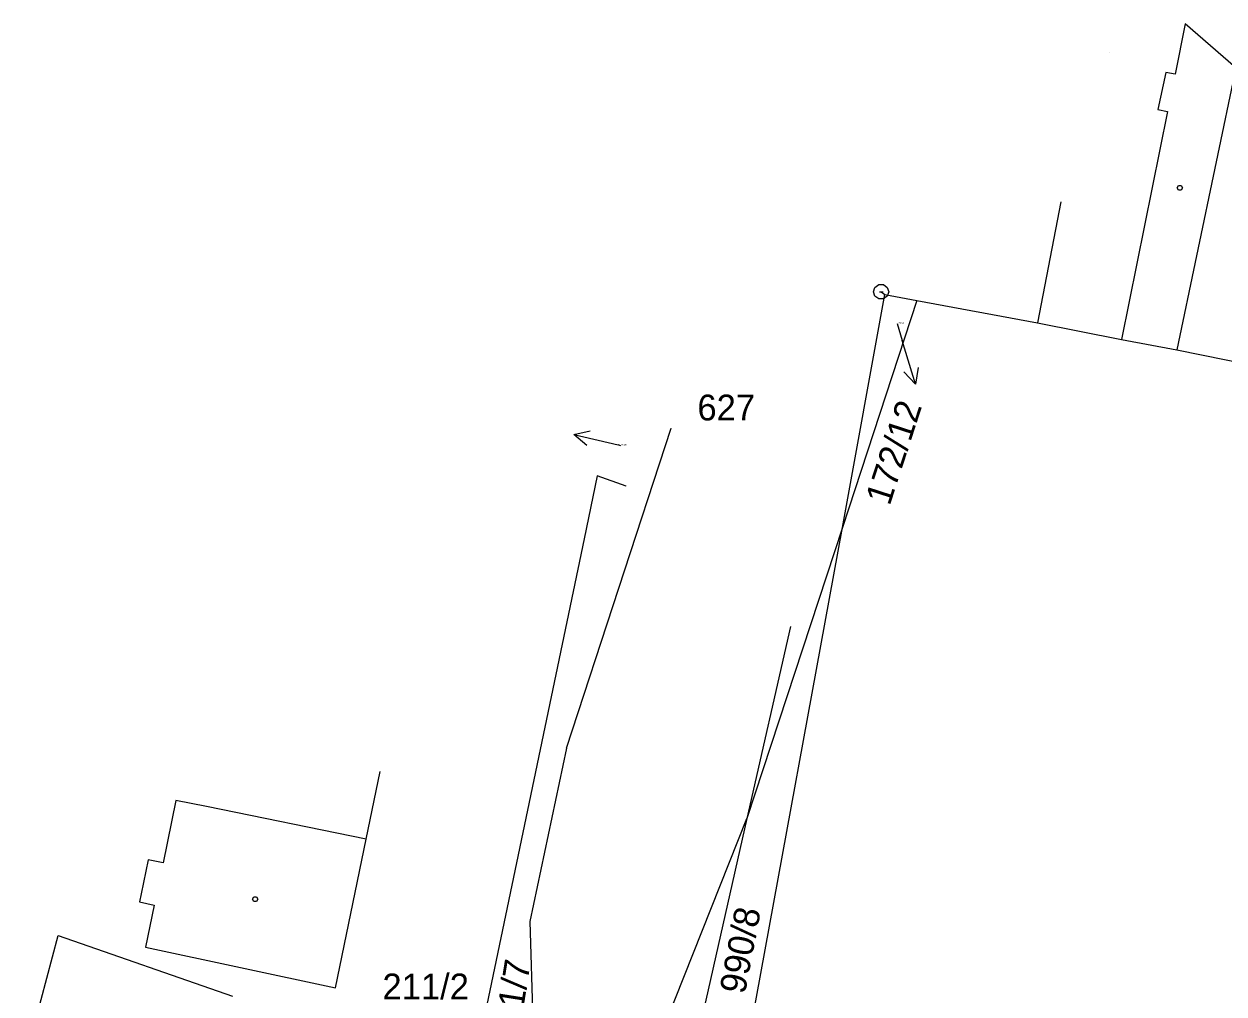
# Model space of a CAD drawing. Extents: x -755359 to -754474, y -1162585 to -1161655.
# Drawn here: x -755066.2 to -754987.3, y -1161776.6 to -1161712.8 of the extents above; entities that cross this region are included whole.
import ezdxf

# ---------------------------------------------------------------- set-up
doc = ezdxf.new("R2010")
doc.units = 0
for name, color, linetype in [('Vrstva 1', 7, 'Continuous'), ('Vrstva 12', 7, 'Continuous'), ('Vrstva 2', 7, 'Continuous'), ('Vrstva 4', 7, 'Continuous'), ('Vrstva 5', 7, 'Continuous'), ('Vrstva 7', 7, 'Continuous'), ('Vrstva 8', 7, 'Continuous')]:
    doc.layers.add(name, color=color, linetype=linetype)

msp = doc.modelspace()

# ---------------------------------------------------------------- linework, layer by layer
at = {"layer": 'Vrstva 1'}
for p, q in [((-754986.49, -1161715.65), (-754989.82, -1161712.77)), ((-754989.82, -1161712.77), (-754989.82, -1161712.77)), ((-754986.49, -1161715.65), (-754990.38, -1161734.22)), ((-755009.83, -1161730.4), (-755009.58, -1161730.57)), ((-755009.83, -1161730.4), (-755009.83, -1161730.4)), ((-755012.38, -1161745.91), (-755009.58, -1161730.57)), ((-755007.48, -1161730.96), (-755012.38, -1161745.91)), ((-755009.58, -1161730.57), (-755007.48, -1161730.96)), ((-755007.48, -1161730.96), (-754999.54, -1161732.44)), ((-754999.54, -1161732.44), (-754994.03, -1161733.53)), ((-754994.03, -1161733.53), (-754990.38, -1161734.22)), ((-754990.38, -1161734.22), (-754978.64, -1161736.57)), ((-755030.54, -1161760.43), (-755023.66, -1161739.37)), ((-755023.66, -1161739.37), (-755023.66, -1161739.37)), ((-755028.51, -1161742.5), (-755029.37, -1161746.66)), ((-755026.62, -1161743.19), (-755028.51, -1161742.5)), ((-755028.51, -1161742.5), (-755028.51, -1161742.5)), ((-755028.51, -1161742.5), (-755028.51, -1161742.5)), ((-755026.62, -1161743.19), (-755026.62, -1161743.19)), ((-755018.69, -1161780.44), (-755012.38, -1161745.91)), ((-755012.38, -1161745.91), (-755018.66, -1161765.05)), ((-755029.37, -1161746.66), (-755036.5, -1161780.73)), ((-755029.37, -1161746.66), (-755029.37, -1161746.66)), ((-755015.79, -1161752.42), (-755018.66, -1161765.05)), ((-755015.79, -1161752.42), (-755015.79, -1161752.42)), ((-755030.54, -1161760.43), (-755032.94, -1161771.83)), ((-755043.71, -1161766.41), (-755042.79, -1161761.96)), ((-755042.79, -1161761.96), (-755042.79, -1161761.96)), ((-755023.99, -1161778.44), (-755018.66, -1161765.05)), ((-755045.73, -1161776.2), (-755043.71, -1161766.41)), ((-755058.51, -1161770.01), (-755058.63, -1161770.54)), ((-755058.63, -1161770.54), (-755057.66, -1161770.75)), ((-755058.51, -1161770.01), (-755058.51, -1161770.01)), ((-755057.66, -1161770.75), (-755058.23, -1161773.52)), ((-755032.94, -1161771.83), (-755032.59, -1161783.86)), ((-755066.23, -1161781.24), (-755063.99, -1161772.75)), ((-755063.99, -1161772.75), (-755063.99, -1161772.75)), ((-755063.99, -1161772.75), (-755052.51, -1161776.75)), ((-755058.23, -1161773.52), (-755045.73, -1161776.2))]:
    msp.add_line(p, q, dxfattribs=at)
at = {"layer": 'Vrstva 12'}
for p, q in [((-754998, -1161724.47), (-754998, -1161724.47)), ((-754998, -1161724.47), (-754998, -1161724.47)), ((-755043.71, -1161766.41), (-755042.79, -1161761.96)), ((-755042.79, -1161761.96), (-755042.79, -1161761.96)), ((-755043.71, -1161766.41), (-755054.23, -1161764.27)), ((-755054.23, -1161764.27), (-755054.23, -1161764.27))]:
    msp.add_line(p, q, dxfattribs=at)
at = {"layer": 'Vrstva 4'}
for p, q in [((-754989.82, -1161712.77), (-754990.49, -1161716.08)), ((-754994.8, -1161714.66), (-754994.8, -1161714.66)), ((-754994.8, -1161714.66), (-754994.8, -1161714.66)), ((-754991.11, -1161715.96), (-754991.62, -1161718.4)), ((-754990.49, -1161716.08), (-754991.11, -1161715.96)), ((-754990.99, -1161718.52), (-754994.03, -1161733.53)), ((-754991.62, -1161718.4), (-754990.99, -1161718.52)), ((-754998, -1161724.47), (-754999.54, -1161732.44)), ((-754998, -1161724.47), (-754998, -1161724.47)), ((-754998, -1161724.47), (-754998, -1161724.47)), ((-755056.23, -1161763.86), (-755057.08, -1161767.98)), ((-755054.23, -1161764.27), (-755056.23, -1161763.86)), ((-755043.71, -1161766.41), (-755054.23, -1161764.27)), ((-755054.23, -1161764.27), (-755054.23, -1161764.27)), ((-755018.66, -1161765.05), (-755021.88, -1161779.23)), ((-755058.05, -1161767.78), (-755058.51, -1161770.01)), ((-755057.08, -1161767.98), (-755058.05, -1161767.78))]:
    msp.add_line(p, q, dxfattribs=at)
at = {"layer": 'Vrstva 5'}
for points in [[(-754990.09, -1161723.4), (-754990, -1161723.55), (-754990.09, -1161723.7), (-754990.27, -1161723.7), (-754990.36, -1161723.55), (-754990.27, -1161723.4)], [(-755050.93, -1161770.21), (-755050.84, -1161770.36), (-755050.93, -1161770.51), (-755051.11, -1161770.51), (-755051.2, -1161770.36), (-755051.11, -1161770.21)]]:
    msp.add_lwpolyline(points, close=True, dxfattribs=at)
at = {"layer": 'Vrstva 7'}
for p, q in [((-755008.79, -1161732.49), (-755008.45, -1161733.6)), ((-755007.574, -1161736.469), (-755008.45, -1161733.6)), ((-755030.063, -1161739.795), (-755027.14, -1161740.47)), ((-755026.95, -1161740.52), (-755027.14, -1161740.47))]:
    msp.add_line(p, q, dxfattribs=at)
for points in [[(-755007.388, -1161735.367), (-755007.574, -1161736.469), (-755008.344, -1161735.659)], [(-755029.201, -1161740.507), (-755030.063, -1161739.795), (-755028.976, -1161739.533)]]:
    msp.add_lwpolyline(points, dxfattribs=at)
at = {"layer": 'Vrstva 8'}
msp.add_line((-755009.95, -1161730.4), (-755009.71, -1161730.4), dxfattribs=at)
msp.add_lwpolyline([(-755009.68, -1161729.92), (-755009.43, -1161730.1), (-755009.33, -1161730.39), (-755009.43, -1161730.68), (-755009.68, -1161730.86), (-755009.99, -1161730.86), (-755010.24, -1161730.68), (-755010.34, -1161730.39), (-755010.24, -1161730.1), (-755009.99, -1161729.92)], close=True, dxfattribs=at)

# ---------------------------------------------------------------- texts
at = {"layer": 'Vrstva 2'}
for s, p in [('172/12', (-755008.767, -1161732.49)), ('991/8', (-755026.936, -1161740.52))]:
    msp.add_text(s, height=0.1, dxfattribs=at).set_placement(p)
msp.add_text('990/8', height=1.7, rotation=79.18277, dxfattribs=at).set_placement((-755018.805, -1161776.667))
at = {"layer": 'Vrstva 7'}
for s, rotation, p in [('172/12', 72.02079, (-755009.278, -1161744.523)), ('991/7', 81.01623, (-755033.773, -1161780.106))]:
    msp.add_text(s, height=1.7, rotation=rotation, dxfattribs=at).set_placement(p)
msp.add_text('211/2', height=1.7, dxfattribs=at).set_placement((-755042.644, -1161776.96))
at = {"layer": 'Vrstva 8'}
msp.add_text('627', height=1.7, dxfattribs=at).set_placement((-755021.923, -1161738.86))

doc.saveas('drawing.dxf')
